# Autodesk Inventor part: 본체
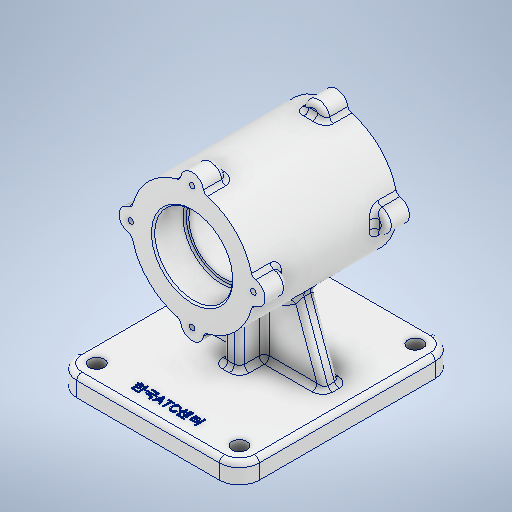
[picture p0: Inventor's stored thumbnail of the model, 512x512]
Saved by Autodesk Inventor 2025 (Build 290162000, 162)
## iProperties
Created: 2024-08
Part Number: 본체
Material: 알루미늄 6061
Document SubType Name: Modeling
Designer: 학생
Density: 2.7 g/cm^3
Appearance: 알루미늄 - 평지
Mass: 1215.39 g
Surface Area: 796.917 cm^2
Volume: 450.145 cm^3
Author: 학생
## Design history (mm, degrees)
sketch "스케치1"
  geometry: C1 r 37 at (0, 0); 1 further point
  constraints: 1 centre point, 1 coincident
  dimensions: "d0" = 37 radius of C1
extrude "돌출1" new body sketch "스케치1" stored distance "d1" = 87; taper "d2" = 0 deg
sketch "스케치2"
  geometry: L1 (0, 61.673)-(0, -61.673); L2 (-58.087, 0)-(58.087, 0); C1 r 7 at (0, 37); C2 r 7 at (37, 0); C3 r 7 at (0, -37); C4 r 7 at (-37, 0); A1 r 37 centre (0, 0) between (0, 37) and (37, 0) reference; 2 further points
  constraints: 4 centre point, 4 end point, 4 point on circle, 4 point on line, 3 equal radius, 2 midpoint, 1 coincident, 1 horizontal, 1 vertical
  dimensions: "d5" = 7 radius of C1
extrude "돌출2" join sketch "스케치2" distance "d6" = 14; taper "d7" = 0 deg
sketch "스케치3"
  geometry: L1 (-55.893, 0)-(55.893, 0); L2 (0, 59.582)-(0, -59.582); C1 r 7 at (0, 37); C2 r 7 at (37, 0); C3 r 7 at (0, -37); C4 r 7 at (-37, 0); A1 r 37 centre (0, 0) between (6.969, 36.338) and (-6.969, 36.338) reference; A2 r 7 centre (0, 37) between (6.969, 36.338) and (-6.969, 36.338) reference; 4 further points
  constraints: 4 centre point, 4 end point, 3 equal radius, 3 point on circle, 3 point on line, 2 coincident, 2 midpoint, 1 horizontal, 1 vertical
  dimensions: "d8" = 7 radius of C1
extrude "돌출3" join sketch "스케치3" distance "d9" = 14; taper "d10" = 0 deg
fillet "모깎기1" dims "d11" = 3
fillet "모깎기2" dims "d12" = 3
node "작업 평면1"
sketch "스케치5"
  geometry: L1 (-55, -60)-(55, -60); L2 (55, -60)-(55, 70); L3 (55, 70)-(-55, 70); L4 (-55, 70)-(-55, -60); L5 (-55, -60)-(55, 70); L6 (55, -60)-(-55, 70); L7 (0, -87.741)-(0, 119.058); 2 further points
  constraints: 14 end point, 2 midpoint, 2 parallel, 2 point on line, 1 horizontal, 1 perpendicular, 1 vertical
  dimensions: "d16" = 110 distance of L1.start L1.end; "d80" = 70 distance from line of L3 point (0, 0); "d81" = 60 distance from line of point (0, 0) L1
extrude "돌출4" join sketch "스케치5" distance "d17" = 12; taper "d18" = 0 deg
fillet "모깎기3" dims "d19" = 12
sketch "스케치13"
  geometry: L1 (0, 62.576)-(0, -113.189); L2 (-15.522, 0)-(15.522, 0); L3 (15.522, 0)-(41, -70); L4 (41, -70)-(-41, -70); L5 (-41, -70)-(-15.522, 0); L6 (43, -70)-(-43, -70) reference; L7 (-55, -70)-(-43, -70) reference; L8 (43, -70)-(55, -70) reference; L9 (-55, -82)-(-55, -70) reference; L10 (55, -70)-(55, -82) reference; 4 further points; 2 other entities
  constraints: 10 end point, 2 midpoint, 2 point on line, 1 collinear, 1 horizontal, 1 parallel, 1 vertical, 3 other
  dimensions: "d88" = 110 deg angle of L7 L5; "d89" = 110 deg angle of L8 L3 (derived); "d90" = 14 distance from line of L4.end L9; "d91" = 14 distance from line of L10 L3.end (derived)
extrude "돌출7" join sketch "스케치13" stored distance "d76" = 10; taper "d77" = 0 deg
sketch "스케치6"
  geometry: L1 (5, 20)-(-5, 20); L2 (-5, 20)-(-5, -20); L3 (-5, -20)-(5, -20); L4 (5, -20)-(5, 20); L5 (5, 20)-(-5, -20); L6 (-5, 20)-(5, -20); 1 further point
  constraints: 12 end point, 2 midpoint, 2 parallel, 1 horizontal, 1 perpendicular
  dimensions: "d26" = 10 distance of L1.start L1.end; "d28" = 40 distance of L1.end L2.end
extrude "돌출6" join sketch "스케치6" stored distance "d29" = 10; taper "d30" = 0 deg
fillet "모깎기6" dims "d31" = 3
fillet "모깎기7" dims "d32" = 3
fillet "모깎기8" dims "d33" = 3
sketch "스케치7"
  geometry: L1 (55, -58)-(55, 48) reference; L2 (-43, -70)-(43, -70) reference; L3 (-55, 48)-(-55, -58) reference; L4 (43, 60)-(-43, 60) reference; L5 (0, 88.759)-(0, -105.778); L6 (-70.638, 0)-(68.291, 0); A1 r 12 centre (43, 48) between (55, 48) and (43, 60) reference; A2 r 12 centre (43, -58) between (43, -70) and (55, -58) reference; A3 r 12 centre (-43, -58) between (-55, -58) and (-43, -70) reference; A4 r 12 centre (-43, 48) between (-43, 60) and (-55, 48) reference; 7 further points
  constraints: 6 coincident, 4 end point, 2 point on line, 2 symmetric about line, 1 horizontal, 1 vertical
  dimensions: "d85" = 70 distance between parallel lines of L2 L6; "d86" = 86 distance of point (43, 48) point (-43, 48) (derived); "d87" = 106 distance of point (43, -58) point (43, 48) (derived)
hole "구멍1" sketch "스케치7" at (-43, -58), (43, -58), (-43, 48), (43, 48) diameter "d34" = 9; stored, may be unused: countersink angle "d38" = 90 deg, drill point angle "d40" = 118 deg; dims "d35" = 6, "d36" = 4, "d37" = 2, "d39" = 8
sketch "스케치8"
  geometry: L1 (0, 52.885)-(0, -52.885); L2 (0, 43.5)-(0, -43.5); L3 (0, -43.5)-(23.5, -43.5); L4 (23.5, -43.5)-(23.5, -24.5); L5 (23.5, -24.5)-(21, -24.5); L6 (21, -24.5)-(21, 24.5); L7 (21, 24.5)-(23.5, 24.5); L8 (23.5, 24.5)-(23.5, 43.5); L9 (23.5, 43.5)-(0, 43.5); L10 (40.263, 0)-(-59.147, 0); 4 further points
  constraints: 20 end point, 7 perpendicular, 2 vertical, 1 coincident, 1 collinear, 1 horizontal, 1 midpoint, 1 point on line, 3 other
  dimensions: "d43" = 87 distance between parallel lines of L3 L9; "d44" = 19 distance of L7.end L8.end; "d45" = 19 distance of L3.end L4.end (derived); "d46" = 42 diameter of L6 L1; "d47" = 47 diameter of L4 L1
revolve "회전1" sketch "스케치8" stored, may be unused: angle "d48" = 90 deg
fillet "모깎기9" dims "d53" = 1
chamfer "모따기1" distance "d54" = 1; stored, may be unused: second distance "d55" = 2, angle "d56" = 45 deg
sketch "스케치9"
  geometry: A1 r 7 centre (0, 37) between (6.889, 38.239) and (-6.889, 38.239) reference; A2 r 7 centre (37, 0) between (38.239, -6.889) and (38.239, 6.889) reference; A3 r 7 centre (0, -37) between (-6.889, -38.239) and (6.889, -38.239) reference; A4 r 7 centre (-37, 0) between (-38.239, 6.889) and (-38.239, -6.889) reference; 5 further points
  constraints: 4 coincident
hole "구멍2" sketch "스케치9" at (0, 37), (37, 0), (0, -37), (-37, 0) diameter "d57" = 3.242; stored, may be unused: countersink angle "d61" = 90 deg, drill point angle "d63" = 118 deg; dims "d58" = 8, "d59" = 4, "d60" = 2, "d62" = 10
node "작업 평면2"
sketch "스케치10"
  geometry: L1 (-102.903, 0)-(102.903, 0); L2 (-43, -70)-(43, -70) reference; 2 further points
  constraints: 2 end point, 2 midpoint, 1 horizontal, 1 vertical alignment, 1 other
  dimensions: "d65" = 58 distance from line of point (0, -58) L1; "d82" = 12 distance from line of point (0, -58) L2 (derived)
feature "엠보싱1" sketch "스케치10" dims "d66" = 0.5, "d67" = 0
fillet "모깎기10" dims "d78" = 3
fillet "모깎기11" dims "d79" = 3
node "솔리드1"
mirror "미러1"
node "투영된 루프1"
feature "A9D066F2-1C7D-4E18-AEED-F7BC21143FA4" dims "d34" = 9, "d35" = 6, "d36" = 4, "d37" = 2, "d38" = 90 deg, "d39" = 8, "d40" = 118 deg
other parameters: "d14" = -82, "d49" = 0.5, "d50" = 2, "d51" = 0, "d64" = 23
